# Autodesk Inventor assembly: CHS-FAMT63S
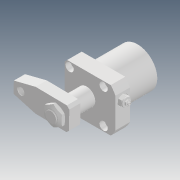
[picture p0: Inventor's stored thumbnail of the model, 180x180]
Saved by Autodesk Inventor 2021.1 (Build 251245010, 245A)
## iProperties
Created: 2019-05
Part Number: CHS-FAMT63S
Description: STEP AP203
Document SubType Name: Assembly
Designer: user
Title: CHS-FAMT63S×°ÅäÌå.STEP
Revision Number: ÈÎºÎ
Sending System: SolidWorks 2017
Preprocessor: SwSTEP 2.0
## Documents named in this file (8)
- D:\Vault_2016\Projekty\Clamptek\Hydraulic\CHS\CHS-63\Inventor\CHS-FAMT63S\CHS-FAMT63S.iam
- D:\Vault_2016\Projekty\Clamptek\Hydraulic\CHS\CHS-63\Inventor\CHS-FAMT63S\M24.ipt
- D:\Vault_2016\Projekty\Clamptek\Hydraulic\CHS\CHS-63\Inventor\CHS-FAMT63S\CHS-63S-01.ipt
- D:\Vault_2016\Projekty\Clamptek\Hydraulic\CHS\CHS-63\Inventor\CHS-FAMT63S\CHS-63S-02_3.ipt
- D:\Vault_2016\Projekty\Clamptek\Hydraulic\CHS\CHS-63\Inventor\CHS-FAMT63S\CHS-FAMT63BT.ipt
- D:\Vault_2016\Projekty\Clamptek\Hydraulic\CHS\CHS-63\Inventor\CHS-FAMT63S\20·§Ìå.ipt
- D:\Vault_2016\Projekty\Clamptek\Hydraulic\CHS\CHS-63\Inventor\CHS-FAMT63S\20µ÷ËÙ¸Ë.ipt
- D:\Vault_2016\Projekty\Clamptek\Hydraulic\CHS\CHS-63\Inventor\CHS-FAMT63S\hex thin nuts-grades ab-chamfered gb(GB_FASTENER_NUT_STNAB M6-S).ipt
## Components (7 placed, 7 different names)
1. M24_1
2. CHS-63S-01_2
3. CHS-63S-02_3_3
4. CHS-FAMT63BT_4
5. 20·§Ìå_5
6. 20µ÷ËÙ¸Ë_6
7. hex thin nuts-grades ab-chamfered gb(GB_FASTENER_NUT_STNAB M6-S)_7
